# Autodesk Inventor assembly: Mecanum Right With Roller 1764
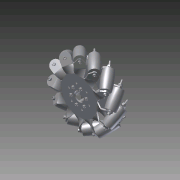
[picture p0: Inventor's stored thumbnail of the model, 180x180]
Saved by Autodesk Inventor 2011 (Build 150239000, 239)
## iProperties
Created: 2011-01
Part Number: Mecanum Right With Roller 1764
Document SubType Name: Assembly
Designer: dfranz
Author: dfranz
Translation Standard: STEP AP203
FileName: //Amserv/amserver/AndyMark/Products/Wheel Mecanum/8 Mecanum Wheel/8 mecanum right with roller.stp
PreProcessor: Unknown
PostProcessor: Build: 239, Release: 2011 RTM - Date: Wed 02/17/2010
Sent Units: millimeter
Uncertainty: 0.001
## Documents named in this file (9)
- R:\CAD Archives\Wheels\Mecanum\Imported Components\8-mecanum-right-with-roller\Mecanum Right With Roller 1764.iam
- R:\CAD Archives\Wheels\Mecanum\Imported Components\8-mecanum-right-with-roller\washer0.ipt
- R:\CAD Archives\Wheels\Mecanum\Imported Components\8-mecanum-right-with-roller\#10 LockNut1.ipt
- R:\CAD Archives\Wheels\Mecanum\Imported Components\8-mecanum-right-with-roller\MBC Bushing MU04TH4.ipt
- R:\CAD Archives\Wheels\Mecanum\Imported Components\8-mecanum-right-with-roller\Mid Roller III2.ipt
- R:\CAD Archives\Wheels\Mecanum\Imported Components\8-mecanum-right-with-roller\SHCS 10-32x3_SHCS 10-32x4.ipt
- R:\CAD Archives\Wheels\Mecanum\Imported Components\8-mecanum-right-with-roller\Middle Axle3.ipt
- R:\CAD Archives\Wheels\Mecanum\Imported Components\8-mecanum-right-with-roller\Spacer AA.ipt
- R:\CAD Archives\Wheels\Mecanum\Imported Components\8-mecanum-right-with-roller\8 Mecanum Plate Right.ipt
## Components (116 placed, 8 different names)
1. washer0:1
2. washer0:2
3. washer0:3
4. washer0:4
5. washer0:5
6. washer0:6
7. washer0:7
8. washer0:8
9. washer0:9
10. washer0:10
11. washer0:11
12. washer0:12
13. washer0:13
14. washer0:14
15. washer0:15
16. washer0:16
17. washer0:17
18. washer0:18
19. washer0:19
20. washer0:20
21. washer0:21
22. washer0:22
23. washer0:23
24. washer0:24
25. #10 LockNut1:1
26. #10 LockNut1:2
27. #10 LockNut1:3
28. #10 LockNut1:4
29. #10 LockNut1:5
30. #10 LockNut1:6
31. #10 LockNut1:7
32. #10 LockNut1:8
33. #10 LockNut1:9
34. #10 LockNut1:10
35. #10 LockNut1:11
36. #10 LockNut1:12
37. #10 LockNut1:13
38. #10 LockNut1:14
39. #10 LockNut1:15
40. #10 LockNut1:16
41. #10 LockNut1:17
42. #10 LockNut1:18
43. MBC Bushing MU04TH4:1
44. MBC Bushing MU04TH4:2
45. MBC Bushing MU04TH4:3
46. MBC Bushing MU04TH4:4
47. MBC Bushing MU04TH4:5
48. MBC Bushing MU04TH4:6
49. MBC Bushing MU04TH4:7
50. MBC Bushing MU04TH4:8
51. MBC Bushing MU04TH4:9
52. MBC Bushing MU04TH4:10
53. MBC Bushing MU04TH4:11
54. MBC Bushing MU04TH4:12
55. MBC Bushing MU04TH4:13
56. MBC Bushing MU04TH4:14
57. MBC Bushing MU04TH4:15
58. MBC Bushing MU04TH4:16
59. MBC Bushing MU04TH4:17
60. MBC Bushing MU04TH4:18
61. MBC Bushing MU04TH4:19
62. MBC Bushing MU04TH4:20
63. MBC Bushing MU04TH4:21
64. MBC Bushing MU04TH4:22
65. MBC Bushing MU04TH4:23
66. MBC Bushing MU04TH4:24
67. Mid Roller III2:1
68. Mid Roller III2:2
69. Mid Roller III2:3
70. Mid Roller III2:4
71. Mid Roller III2:5
72. Mid Roller III2:6
73. Mid Roller III2:7
74. Mid Roller III2:8
75. Mid Roller III2:9
76. Mid Roller III2:10
77. Mid Roller III2:11
78. Mid Roller III2:12
79. SHCS 10-32x3_SHCS 10-32x4:1
80. SHCS 10-32x3_SHCS 10-32x4:2
81. SHCS 10-32x3_SHCS 10-32x4:3
82. SHCS 10-32x3_SHCS 10-32x4:4
83. SHCS 10-32x3_SHCS 10-32x4:5
84. SHCS 10-32x3_SHCS 10-32x4:6
85. SHCS 10-32x3_SHCS 10-32x4:7
86. SHCS 10-32x3_SHCS 10-32x4:8
87. SHCS 10-32x3_SHCS 10-32x4:9
88. SHCS 10-32x3_SHCS 10-32x4:10
89. SHCS 10-32x3_SHCS 10-32x4:11
90. SHCS 10-32x3_SHCS 10-32x4:12
91. SHCS 10-32x3_SHCS 10-32x4:13
92. SHCS 10-32x3_SHCS 10-32x4:14
93. SHCS 10-32x3_SHCS 10-32x4:15
94. SHCS 10-32x3_SHCS 10-32x4:16
95. SHCS 10-32x3_SHCS 10-32x4:17
96. SHCS 10-32x3_SHCS 10-32x4:18
97. Middle Axle3:1
98. Middle Axle3:2
99. Middle Axle3:3
100. Middle Axle3:4
101. Middle Axle3:5
102. Middle Axle3:6
103. Middle Axle3:7
104. Middle Axle3:8
105. Middle Axle3:9
106. Middle Axle3:10
107. Middle Axle3:11
108. Middle Axle3:12
109. Spacer AA:1
110. Spacer AA:2
111. Spacer AA:3
112. Spacer AA:4
113. Spacer AA:5
114. Spacer AA:6
115. 8 Mecanum Plate Right:1
116. 8 Mecanum Plate Right:2
